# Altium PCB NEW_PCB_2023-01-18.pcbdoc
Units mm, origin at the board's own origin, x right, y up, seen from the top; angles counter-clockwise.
Board outline 133.88 x 57.65 mm, 2 copper layers (Top Layer, Bottom Layer); 16 components, 61 nets, 88 pads, 5 vias.
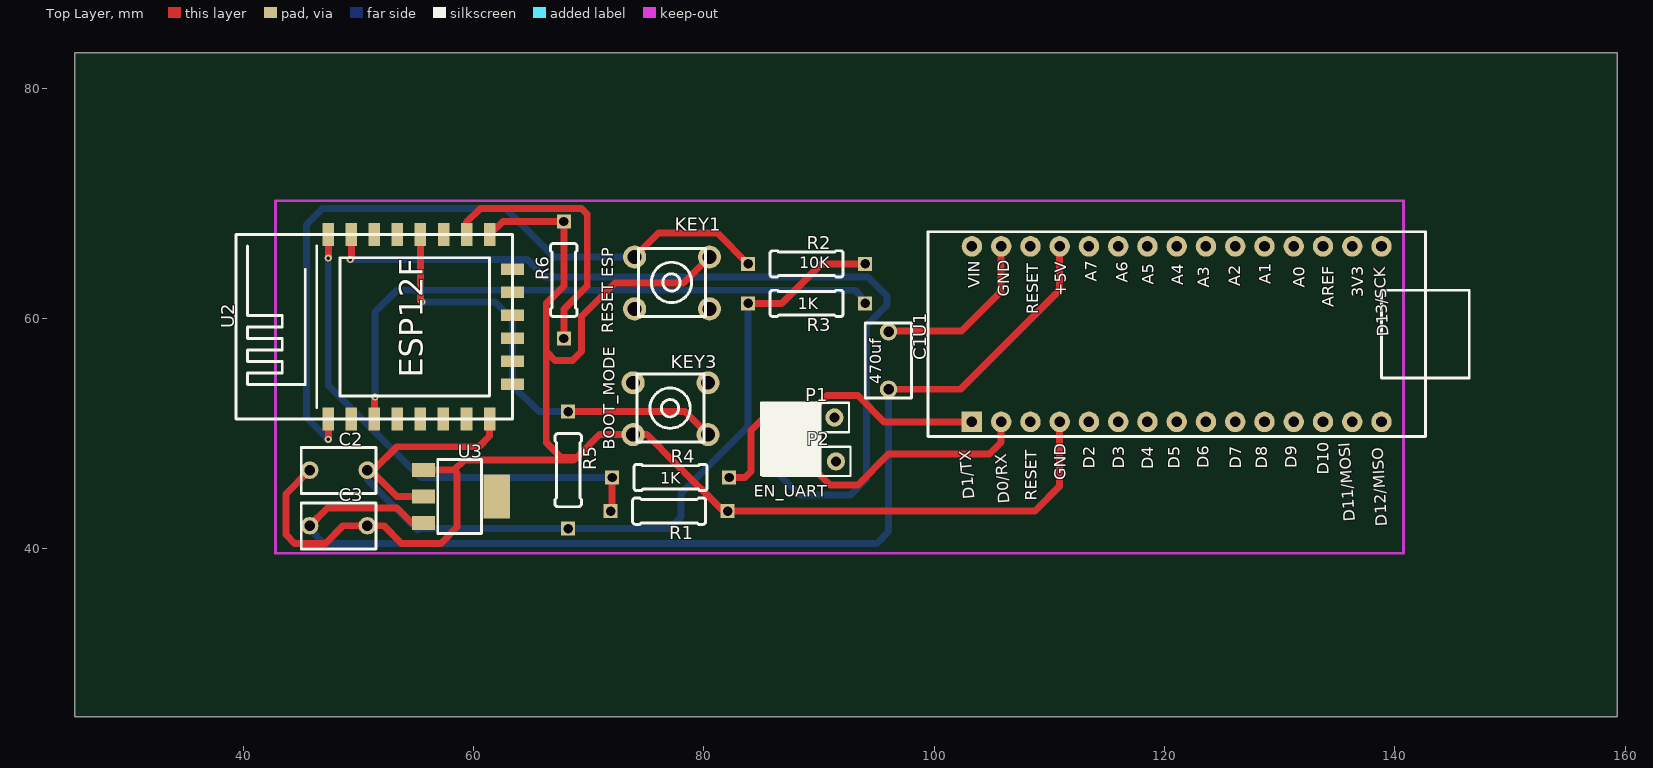
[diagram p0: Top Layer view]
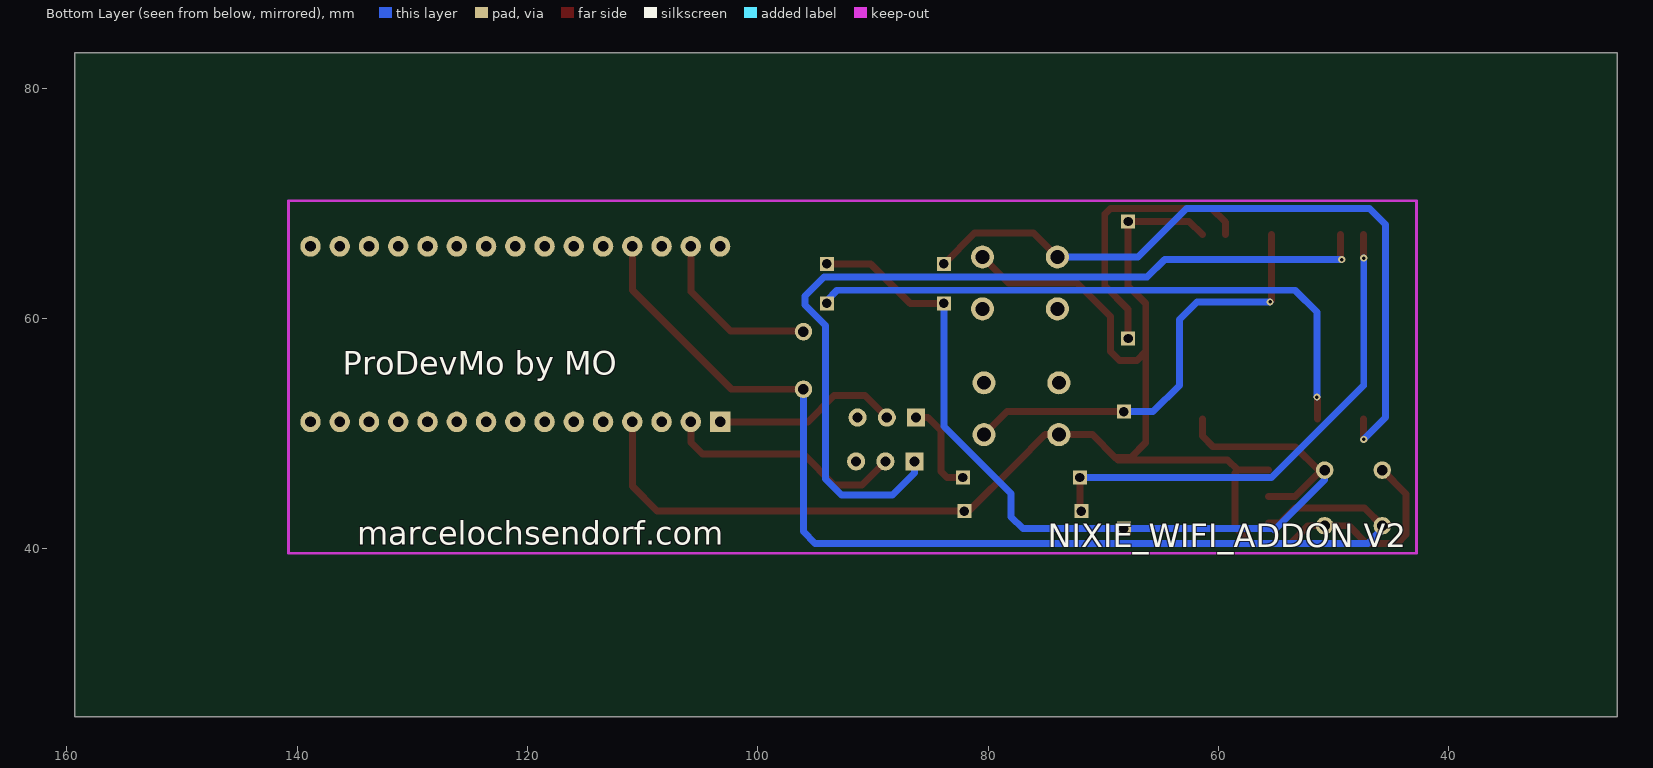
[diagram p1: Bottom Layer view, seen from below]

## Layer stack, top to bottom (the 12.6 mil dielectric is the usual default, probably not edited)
Top Layer: signal copper (thickness not stored)
Dielectric: dielectric 0.32, FR-4, Dk 4.8
Bottom Layer: signal copper (thickness not stored)

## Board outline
159.28,25.4 25.4,25.4 25.4,83.048 159.28,83.048

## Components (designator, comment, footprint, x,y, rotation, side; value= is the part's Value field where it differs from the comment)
C1 "15nF" CAP-CBB-6.5*4.0 96.034,56.353 r270 top
C2 "15nF" CAP-CBB-6.5*4.0 48.282,46.828 r0 top
C3 "15nF" CAP-CBB-6.5*4.0 48.282,42.002 r0 top
KEY1 "button6*6*8" KEY-6.0*6.0-2 77.238,63.084 r0 top
KEY3 "button6*6*8" KEY-6.0*6.0-2 77.111,52.162 r0 top
P1 "Header-Male-2.54_1x3" HDR-3X1/2.54 88.795,51.4 r0 top
P2 "Header-Male-2.54_1x3" HDR-3X1/2.54 88.922,47.59 r0 top
R1 "RESISTOR" RTH025W#1 76.985,43.271 r180 top
R2 "RESISTOR" RTH025W#1 88.922,64.735 r0 top
R3 "RESISTOR" RTH025W#2 88.922,61.306 r180 top
R4 "RESISTOR" RTH025W#1 77.111,46.193 r0 top
R5 "RESISTOR" RTH025W#3 68.221,46.828 r270 top
R6 "RESISTOR" RTH025W#3 67.84,63.338 r90 top
U1 "ARDUINO_NANO" ARDUINO_NANO 121.053,58.639 r90 top
U2 "ESP-12F(ESP8266MOD)" ESP-12F(ESP8266MOD) 55.394,59.274 r90 top
U3 "LM1117MPX-ADJ" SOT-223 58.823,44.542 r0 top

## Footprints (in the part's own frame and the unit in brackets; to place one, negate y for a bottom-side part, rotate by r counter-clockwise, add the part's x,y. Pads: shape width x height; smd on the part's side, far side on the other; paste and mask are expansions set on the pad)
ARDUINO_NANO [mil]
  rect 70x70 hole 36: 1(-300,700)
  round 70 hole 36: 2(-300,600) 3(-300,500) 4(-300,400) 5(-300,300) 6(-300,200) 7(-300,100) 8(-300,0) 9(-300,-100) 10(-300,-200) 11(-300,-300) 12(-300,-400) 13(-300,-500) 14(-300,-600) 15(-300,-700) 16(300,-700) 17(300,-600) 18(300,-500) 19(300,-400) 20(300,-300) 21(300,-200) 22(300,-100) 23(300,0) 24(300,100) 25(300,200) 26(300,300) 27(300,400) 28(300,500) 29(300,600) 30(300,700)
  silkscreen extent -350,-1000 350,850
CAP-CBB-6.5*4.0 [mil]
  round 60 hole 36: 1(-98.4,0) 2(98.4,0)
  silkscreen extent -128,-80 128,78
ESP-12F(ESP8266MOD) [mm]
  rect 2x1 smd: 1(-8.002,8) 2(-8.002,6) 3(-8.002,4.001) 4(-8.002,2.001) 5(-8.002,0) 6(-8.002,-1.999) 7(-8.002,-3.999) 8(-8.001,-5.999) 15(7.999,-6.005) 16(8,-4.001) 17(8.002,-2.003) 18(8.001,-0.002) 19(8,1.998) 20(8.001,3.998) 21(8,5.998) 22(8.001,7.998)
  rect 1x2 smd: 9(-5,-8) 10(-3.002,-7.999) 11(-1.003,-7.999) 12(0.997,-7.999) 13(2.997,-7.999) 14(4.997,-8)
  silkscreen extent -8,-8 8,16
HDR-3X1/2.54 [mil]
  rect 62x62 hole 35: 1(-100,0)
  round 62 hole 35: 2(0,0) 3(100,0)
  silkscreen extent -150,-50 150,50
KEY-6.0*6.0-2 [mm]
  round 2 hole 1.2: 1(3.25,-2.25) 2(-3.25,-2.25) 3(3.25,2.25) 4(-3.25,2.25)
  silkscreen extent -2.9,-2.9 2.9,3
RTH025W#1 [mil]
  rect 47.7x47.7 hole 32: 1(-199.95,-0.05) 2(200.05,-0.05)
  silkscreen extent -125,-45 125,45
RTH025W#2 [mil]
  rect 47.7x47.7 hole 32: 1(-200.05,0.05) 2(199.95,0.05)
  silkscreen extent -125,-45 125,45
RTH025W#3 [mil]
  rect 47.7x47.7 hole 32: 1(-200,0) 2(200,0)
  silkscreen extent -125,-45 125,45
SOT-223 [mm]
  rect 2x1.2 smd: 1(-3.175,2.3) 2(-3.175,0) 3(-3.175,-2.3)
  rect 2.3x3.8 smd: 4(3.175,0)
  silkscreen extent -1.93,-3.2 1.87,3.2

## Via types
v1: diameter 0.62, hole 0.305, Top Layer to Bottom Layer, tented both sides, 5 vias

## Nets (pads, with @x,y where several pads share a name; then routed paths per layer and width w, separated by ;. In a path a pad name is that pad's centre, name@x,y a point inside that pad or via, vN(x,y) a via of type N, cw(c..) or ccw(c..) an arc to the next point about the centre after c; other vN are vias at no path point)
KEY1_1: KEY1.1
KEY1_2: KEY1.2
KEY1_4: KEY1.4 R2.1 U2.1 | length 63.9
  Top Layer w0.6: v1@47.393,49.496 U2.1 ; KEY1.4 76.056,67.402 81.175,67.402 R2.1@83.842,64.735
  Bottom Layer w0.6: v1(47.393,49.495) 45.488,51.4 45.488,68.164 46.885,69.561 62.762,69.561 66.989,65.334 KEY1.4
KEY3_1: KEY3.1 R5.1 U2.18 | length 38.9
  Top Layer w0.6: U2.18 55.396,61.558 v1(55.521,61.433) ; R5.1 78.365,51.908 KEY3.1
  Bottom Layer w0.6: v1(55.521,61.433) 61.871,61.433 63.395,59.909 63.395,54.194 65.681,51.908 R5.1
KEY3_3: KEY3.3
KEY3_4: KEY3.4
P1_1: P1.1 R4.2 | length 8.3
  Top Layer w0.6: R4.2@82.191,46.193 83.588,46.193 84.096,46.701 84.096,50.257 85.239,51.4 P1.1
P1_3: P1.3
P2_1: P2.1 U2.21 | length 76.9
  Top Layer w0.6: v1(49.298,65.116) 49.396,65.215 U2.21
  Bottom Layer w0.6: v1(49.298,65.116) 64.665,65.116 66.189,63.592 94.256,63.592 95.907,61.941 95.907,61.179 94.129,59.401 94.129,46.066 92.732,44.669 88.287,44.669 86.509,46.447 86.382,46.574 P2.1
P2_3: P2.3
R1_2: R1.2 R4.1 U2.22 | length 44
  Top Layer w0.6: v1(47.393,65.243) 47.396,65.247 U2.22 ; R1.2 72.031,43.399 R4.1@72.031,46.193
  Bottom Layer w0.6: v1(47.393,65.243) 47.393,54.194 55.394,46.193 R4.1@72.031,46.193
R2_2: C2.2 R2.2 R3.2 R5.2 U2.8 U3.2 | length 82
  Top Layer w0.6: U3.2 53.362,44.542 51.076,46.828 C2.2 51.33,46.828 53.362,48.86 60.474,48.86 61.363,49.749 61.393,49.78 U2.8 ; R3.2@83.842,61.306 86.763,61.306 90.192,64.735 R2.2@94.002,64.735
  Bottom Layer w0.6: C2.2@50.781,46.828 50.781,45.98 55.14,41.621 55.267,41.748 R5.2 76.984,41.748 78,42.764 78,44.796 80.54,47.336 83.842,50.638 R3.2@83.842,61.306
S$21: 
S$23: 
U1_1: P1.2 U1.1 | length 16.2
  Top Layer w0.6: P1.2 90.7,53.305 93.367,53.305 95.653,51.019 U1.1
U1_2: P2.2 U1.2 | length 21
  Top Layer w0.6: P2.2 90.954,45.558 93.367,45.558 96.034,48.225 104.797,48.225 105.813,49.241 U1.2
U1_3: U1.3
U1_4: C2.1 C3.2 KEY1.3 KEY3.2 R1.1 R6.2 U1.4 U2.15 U3.1 | length 144.2
  Top Layer w0.6: C2.1 43.71,44.756 43.71,41.24 44.472,40.478 47.139,40.478 48.663,42.002 C3.2 52.219,42.002 53.743,40.478 57.172,40.478 58.569,41.875 58.569,46.574 58.315,46.828 ; U3.1@55.648,46.854 58.301,46.854 58.315,46.828 ; U2.15 62.544,68.418 R6.2 67.84,62.83 66.316,61.306 66.316,57.115 ; KEY1.3 78.238,63.084 72.285,63.084 69.364,60.163 69.364,57.115 68.602,56.353 67.078,56.353 66.316,57.115 ; U1.4 110.893,45.431 108.734,43.272 R1.1 81.683,43.272 77.619,47.336 75.042,49.913 KEY3.2 70.924,49.913 68.968,47.946 ; 58.315,46.828 59.204,47.717 68.729,47.717 68.968,47.946 ; 66.316,57.115 66.316,49.241 67.611,47.946 68.968,47.946
U1_5: U1.5
U1_6: U1.6
U1_7: U1.7
U1_8: U1.8
U1_9: U1.9
U1_10: U1.10
U1_11: U1.11
U1_12: U1.12
U1_13: U1.13
U1_14: U1.14
U1_15: U1.15
U1_16: U1.16
U1_17: U1.17
U1_18: U1.18
U1_19: U1.19
U1_20: U1.20
U1_21: U1.21
U1_22: U1.22
U1_23: U1.23
U1_24: U1.24
U1_25: U1.25
U1_26: U1.26
U1_27: C1.2 C3.1 U1.27 U3.3 | length 97.1
  Top Layer w0.6: C3.1 47.306,43.526 53.362,43.526 54.646,42.242 U3.3 ; C1.2 102.297,53.854 110.893,62.449 U1.27
  Bottom Layer w0.6: C3.1 45.782,41.708 47.012,40.478 95.018,40.478 96.034,41.494 C1.2
U1_28: U1.28
U1_29: C1.1 U1.29 | length 15.2
  Top Layer w0.6: C1.1 96.074,58.893 102.384,58.893 105.813,62.322 U1.29
U1_30: U1.30
U2_2: U2.2
U2_3: R3.1 U2.3 | length 53.3
  Top Layer w0.6: U2.3@51.393,51.273 51.393,53.115 v1(51.457,53.178)
  Bottom Layer w0.6: v1(51.457,53.178) 51.457,60.544 53.362,62.449 93.113,62.449 94.002,61.56 R3.1@94.002,61.306
U2_4: U2.4
U2_5: U2.5
U2_6: U2.6
U2_7: U2.7
U2_9: U2.9
U2_10: U2.10
U2_11: U2.11
U2_12: U2.12
U2_13: U2.13
U2_14: U2.14
U2_16: R6.1 U2.16 | length 23.9
  Top Layer w0.6: U2.16 59.395,68.355 60.601,69.561 69.364,69.561 69.872,69.053 69.872,62.83 67.84,60.798 R6.1
U2_17: U2.17
U2_19: U2.19
U2_20: U2.20
U3_4: U3.4

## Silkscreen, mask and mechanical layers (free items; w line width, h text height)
Top Overlay:
  rectangle: 84.858,46.32 90.192,52.67
  text "10K" at 88.287,64.362 h1
  text "1K" at 88.16,60.806 h1
  text "RESET ESP" at 72.15,58.728 h1 r90
  text "470uf" at 95.391,54.283 h1 r90
  text "BOOT_MODE" at 72.277,48.606 h1 r90
  text "1K" at 76.222,45.655 h1
  text "EN_UART" at 84.35,44.512 h1
Bottom Overlay:
  text "ProDevMo by MO" at 136.018,55.118 h2.03
  text "marcelochsendorf.com" at 134.769,40.351 h2.03
  text "NIXIE_WIFI_ADDON V2" at 74.811,40.132 h2.03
